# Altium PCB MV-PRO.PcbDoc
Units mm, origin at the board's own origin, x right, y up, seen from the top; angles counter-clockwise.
Board outline 39 x 25 mm, 2 copper layers (Top Layer, Bottom Layer); 9 components, 6 nets, 20 pads, 0 vias.
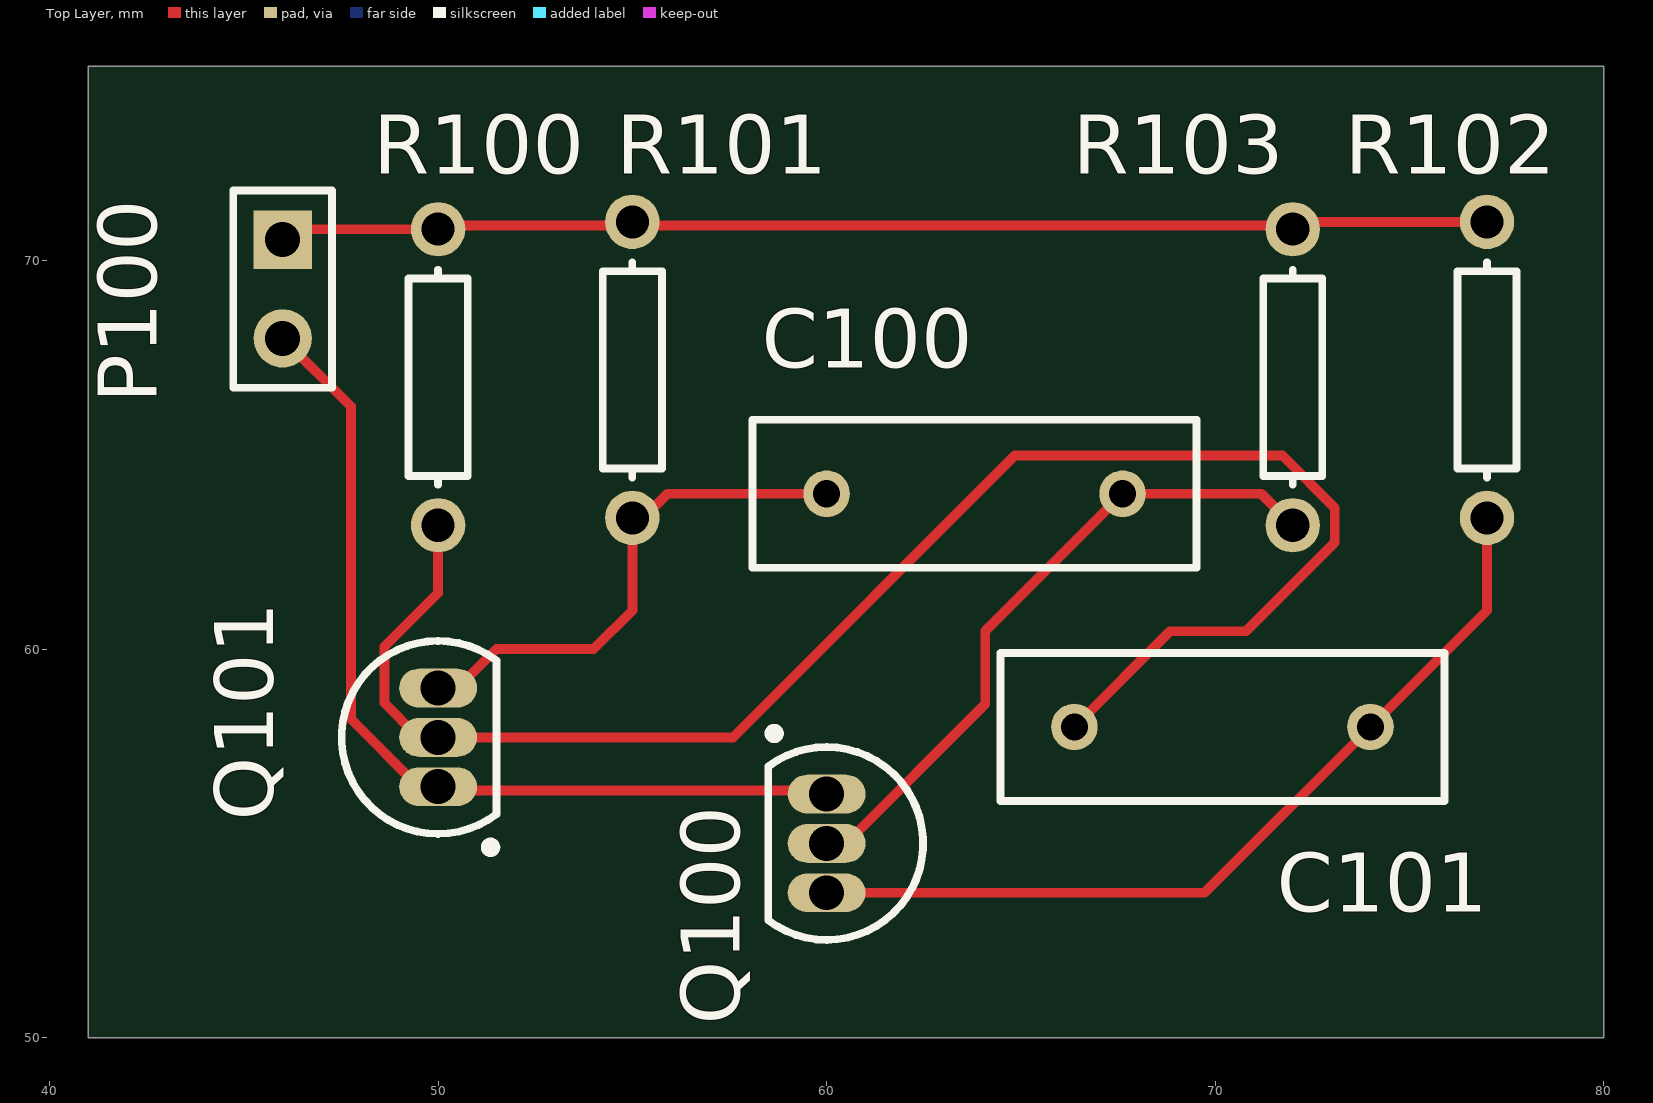
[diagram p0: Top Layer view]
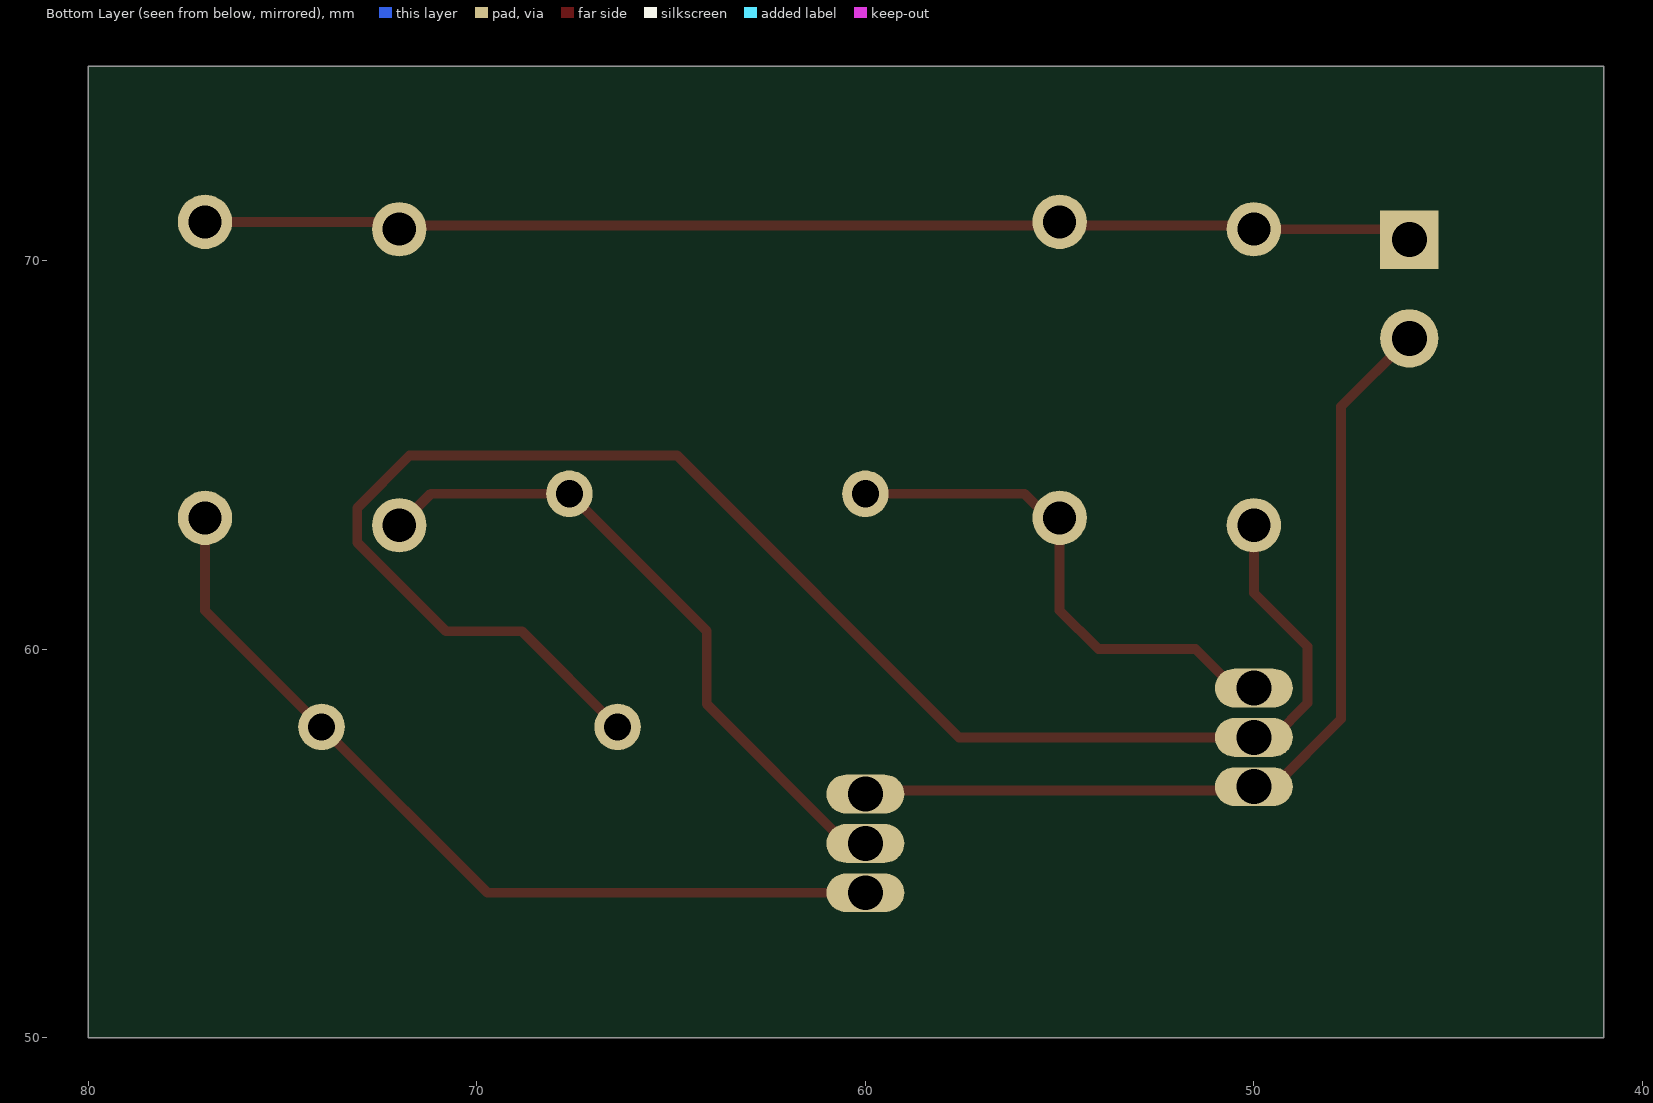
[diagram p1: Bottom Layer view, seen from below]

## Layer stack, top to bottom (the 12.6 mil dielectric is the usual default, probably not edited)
Top Solder: solder mask 0.0102, Solder Resist, Dk 3.5
Top Layer: signal copper 0.0356
Dielectric 1: dielectric 0.32, FR-4, Dk 4.8
Bottom Layer: signal copper 0.0356
Bottom Solder: solder mask 0.0102, Solder Resist, Dk 3.5

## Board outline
41,50 80,50 80,75 41,75

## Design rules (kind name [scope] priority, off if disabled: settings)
Clearance [All] p1: gap=0.254 ignorepadtopadclearanceinfootprint=FALSE except(0: Arc-Hole Track-Hole SMDPad-Hole THPad-Hole Via-Hole Fill-Hole Poly-Hole Region-Hole Text-Hole)
PolygonConnect [All] p1: connectstyle=Relief reliefconductorwidth=0.254 reliefentries=4 polygonreliefangle="90 Angle" airgapwidth=0.254
RoutingVias [All] p1: holewidth=0.711 width=1.27 viastyle="Through Hole" minholewidth=0.711 minwidth=1.27 maxholewidth=0.711 maxwidth=1.27
SolderMaskExpansion [All] p1: expansion=0.102 istentingtop=FALSE
Width [All] p1: maxlimit=0.254 minlimit=0.254 preferedwidth=0.254
30 further rules are at their usual default settings.

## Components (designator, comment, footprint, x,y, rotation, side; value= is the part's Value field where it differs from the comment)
C100 "Cap" RAD-0.3 63.81,64 r0 top value=100pF
C101 "Cap" RAD-0.3 70.19,58 r0 top value=100pF
P100 "Header 2" HDR1X2 46,70.54 r270 top
Q100 "2N3904" TO-92A 60,55 r180 top
Q101 "2N3904" TO-92A 50,57.73 r0 top
R100 "Res1" AXIAL-0.3 50,67 r270 top value=1K
R101 "Res1" AXIAL-0.3 55,67.19 r270 top value=1K
R102 "Res1" AXIAL-0.3 77,67.19 r270 top value=1K
R103 "Res1" AXIAL-0.3 72,67 r270 top value=1K

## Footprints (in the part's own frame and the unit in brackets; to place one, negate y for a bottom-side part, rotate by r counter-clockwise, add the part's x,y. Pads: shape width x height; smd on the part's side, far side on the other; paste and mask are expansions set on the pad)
AXIAL-0.3 [mm] "Axial Device, Thru-Hole; 2 Leads; 0.3 in Pin Spacing"
  round 1.4 hole 0.85: 1(-3.81,0) 2(3.81,0)
  silkscreen extent -2.77,-0.76 2.77,0.76
HDR1X2 [mm] "Connector; Header; 2 Position"
  rect 1.5x1.5 hole 0.9: 1(0,0)
  round 1.5 hole 0.9: 2(2.54,0)
  silkscreen extent -1.27,-1.27 3.81,1.27
RAD-0.3 [mm] "Radial Cap, Thru-Hole; 2 Leads; 0.3 in Pin Spacing"
  round 1.2 hole 0.7: 1(-3.81,0) 2(3.81,0)
  silkscreen extent -5.71,-1.91 5.71,1.91
TO-92A [mm] "TO, Flat Index; 3 In-Line, Axial Leads; Body Dia. 4.5mm; Leads 0.51 x 0.48 mm (max)"
  oval 2x1 hole 0.9: 1(0,-1.27) 2(0,0) 3(0,1.27)
  silkscreen extent -2.48,-2.95 1.5,2.48, body extent -2.48,-2.5 1.5,2.5, height 6.86

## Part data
C100 C101: "Capacitor"
P100: "Header, 2-Pin"
Q100 Q101: "NPN General Purpose Amplifier"
R100 R101 R102 R103: "Resistor"

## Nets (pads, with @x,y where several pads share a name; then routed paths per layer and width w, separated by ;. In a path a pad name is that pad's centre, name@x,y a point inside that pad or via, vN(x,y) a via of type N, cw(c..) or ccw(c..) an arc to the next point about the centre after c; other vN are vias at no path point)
NetC100_1: C100.1 Q101.3 R101.2 | length 13.5
  Top Layer w0.254: Q101.3 50.5,59 51.5,60 54,60 55,61 R101.2 55.289,63.38 55.909,64 C100.1
NetC100_2: C100.2 Q100.2 R103.2 | length 17.2
  Top Layer w0.254: Q100.2 60.5,55 64.085,58.585 64.085,60.465 C100.2 71.19,64 R103.2
NetC101_1: C101.1 Q101.2 R100.2 | length 43.1
  Top Layer w0.254: R100.2 50,61.448 48.619,60.067 48.619,58.611 49.5,57.73 Q101.2 57.594,57.73 64.845,64.981 71.738,64.981 73.081,63.638 73.081,62.742 70.8,60.462 68.842,60.462 C101.1
NetC101_2: C101.2 Q100.3 R102.2 | length 22.2
  Top Layer w0.254: Q100.3 69.73,53.73 C101.2 77,61 R102.2@77,63.19
NetP100_1: P100.1 R100.1 R101.1 R102.1 R103.1 | length 31.3
  Top Layer w0.254: P100.1 46.27,70.81 R100.1 50.095,70.905 54.905,70.905 R101.1 55.095,70.905 71.905,70.905 R103.1 72.19,71 R102.1
NetP100_2: P100.2 Q100.1 Q101.1 | length 23.6
  Top Layer w0.254: P100.2 47.753,66.247 47.753,58.207 49.5,56.46 Q101.1 50.095,56.365 59.905,56.365 Q100.1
